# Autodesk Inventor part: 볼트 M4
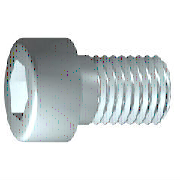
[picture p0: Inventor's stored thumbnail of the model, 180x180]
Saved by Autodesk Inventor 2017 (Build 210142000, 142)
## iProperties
IsCustomPart: 1
Created: 2012-02
Part Number: 볼트 M4
Material: 강철, 연강
Description: 6각머리 태핑 나사
Document SubType Name: Modeling
Standard: KS B 1003
Designer: mduedu
Standards Organization: KS
Language: ko-KR
Size Designation: M 4 x 10
Categories: <MemberInstance><Categories><Category DisplayName="조임쇠" InternalName="e4da775c-781d-43d5-af7c-5136215cf5a6" Mnemonic="FSTN"><Category DisplayName="볼트" InternalN
Density: 7.85 g/cm^3
Appearance: 강철
Mass: 2.0343 g
Surface Area: 3.06255 cm^2
Volume: 0.259146 cm^3
Author: mduedu
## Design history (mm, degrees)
sketch "스케치1"
  geometry: L1 (-1, 0)-(10, 0); L2 (10, 0)-(10, 2); L3 (10, 2)-(1.75, 2); L4 (1.75, 2)-(1.32, 2); L5 (1.32, 2)-(0, 2); L6 (0, 2)-(0, 3.5); L7 (0, 3.5)-(-4, 3.5); L8 (-4, 3.5)-(-4, 1.732); L9 (-4, 1.732)-(-2, 1.732); L10 (-2, 1.732)-(-1, 0); L11 (-6.8, 0)-(12.8, 0) reference; L12 (0, -0.7)-(0, 4.2) reference; L13 (1.75, 2)-(0, 2)
  constraints: 22 end point, 6 parallel, 2 collinear, 2 perpendicular, 1 horizontal, 1 point on line
  dimensions: "d1" = 8.25 distance from line of L3.end L2 (= GEL); "d2" = 0.42952 distance of L4.end L3.end (computed from GAL); "d3" = 4 distance between parallel lines of L8 L6 (= KOH); "d4" = 2 distance of L8.end L9.end (= INTI); "d5" = 60 deg angle of L10 L1; "d6" = 4 diameter of L3 L1 (= GD); "d7" = 4 diameter of L5 L1 (= BDM); "d8" = 3.4641 diameter of L9 L1 (= 1.1547 x SW); "d9" = 7 diameter of L7 L1 (= KOD); "d26" = 10 distance between parallel lines of L12 L2 (= NLG)
revolve "본체" sketch "스케치1" stored, may be unused: angle "d10" = 90 deg
sketch "스케치2"
  geometry: L1 (0, -4.9)-(0, 4.9) reference; L2 (-4.9, 0)-(4.9, 0) reference; L3 (1.732, 0)-(0.866, -1.5); L4 (0.866, -1.5)-(-0.866, -1.5); L5 (-0.866, -1.5)-(-1.732, 0); L6 (-1.732, 0)-(-0.866, 1.5); L7 (-0.866, 1.5)-(0.866, 1.5); L8 (0.866, 1.5)-(1.732, 0); 2 further points
  constraints: 12 end point, 1 coincident, 1 horizontal alignment, 1 point on line, 12 other
extrude "슬롯" join sketch "스케치2" stored distance "d11" = 10; taper "d12" = 0 deg
workplane "Work Plane1"
body "Solid1"
fillet "모깎기1" dims "d17" = 0.4 (= RR)
feature "스레드" dims "d13" = 8.25 (= GEL), "d14" = 0
chamfer "모따기1" distance "d15" = 0.42941 (= -0.5 x SPD + 0.5 x GD); stored, may be unused: second distance "d16" = 0.42941 (= GUL), angle "d27" = 45 deg
other parameters: "GD" = 4 (= NND) [user parameter; used in 2 equation terms], "NLG" = 10 [user parameter; used in 1 equation term], "GEL" = 8.25 [user parameter; used in 2 equation terms], "KOD" = 7 [user parameter; used in 1 equation term], "KOH" = 4 [user parameter; used in 1 equation term], "INTI" = 2 [user parameter; used in 1 equation term], "GAL" = 0.42941 (= 0.61345 x PTC) [user parameter; used in 1 equation term], "GUL" = 0.42941 (= 0.61345 x PTC) [user parameter; used in 1 equation term], "BDM" = 4 (= NND) [user parameter; used in 1 equation term], "SW" = 3 [user parameter; used in 2 equation terms], "RR" = 0.4 [user parameter; used in 1 equation term], "SPD" = 3.14117 (= NND - 1.2269 x PTC) [user parameter; used in 1 equation term], "d19" = 0, "d28" = 0, "d29" = 0, "R" = 0.1 [user parameter], "PHH" = 0.2 [user parameter], "GD1" = 3.14117 (= THREADDIA - 1.2269 x PTC) [user parameter], "THREADDIA" = 4 [user parameter; used in 1 equation term], "FAWI" = 45 deg [user parameter], "TPU" = 14.28571 (computed from PTC) [user parameter], "PTC" = 0.7 [user parameter; used in 5 equation terms], "NND" = 4 [user parameter; used in 3 equation terms], "TOA" = 30 deg [user parameter], "E0" = 3.465 (= 1.155 x SW) [user parameter]
